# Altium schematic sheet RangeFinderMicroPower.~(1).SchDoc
size A
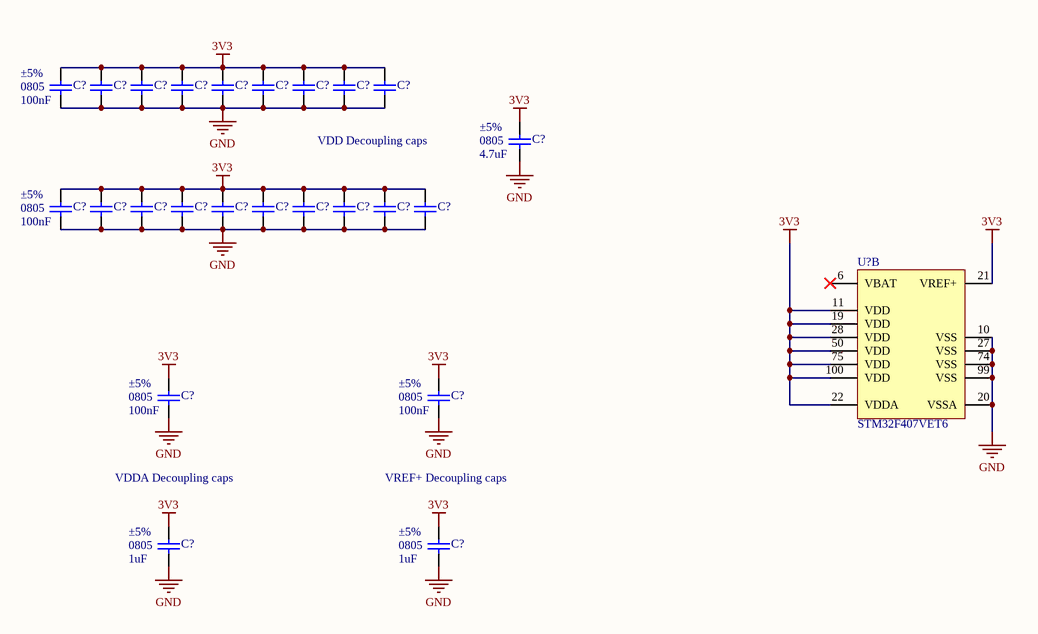
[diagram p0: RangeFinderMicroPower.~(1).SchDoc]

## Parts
(Parts that share a designator on the sheet are numbered #1, #2 ... from top to bottom, then left to right.)
C?#1  value 100nF  Tolerance: ±5%  Case-EIA: 0805  [CAPC0805(2012)100_L]  (hidden comment: CAP 100nF 6.3V 0805(2012))
C?#2  CAP 100nF 6.3V 0805(2012)  [CAPC0805(2012)100_L]  (value not drawn)
C?#3  CAP 100nF 6.3V 0805(2012)  [CAPC0805(2012)100_L]  (value not drawn)
C?#4  CAP 100nF 6.3V 0805(2012)  [CAPC0805(2012)100_L]  (value not drawn)
C?#5  CAP 100nF 6.3V 0805(2012)  [CAPC0805(2012)100_L]  (value not drawn)
C?#6  CAP 100nF 6.3V 0805(2012)  [CAPC0805(2012)100_L]  (value not drawn)
C?#7  CAP 100nF 6.3V 0805(2012)  [CAPC0805(2012)100_L]  (value not drawn)
C?#8  CAP 100nF 6.3V 0805(2012)  [CAPC0805(2012)100_L]  (value not drawn)
C?#9  CAP 100nF 6.3V 0805(2012)  [CAPC0805(2012)100_L]  (value not drawn)
C?#10  value 4.7uF  Case-EIA: 0805  Tolerance: ±5%  [CAPC0805(2012)145_N]  (hidden comment: CAP 4.7uF 6.3V 0805(2012))
C?#11  value 100nF  Tolerance: ±5%  Case-EIA: 0805  [CAPC0805(2012)100_L]  (hidden comment: CAP 100nF 6.3V 0805(2012))
C?#12  CAP 100nF 6.3V 0805(2012)  [CAPC0805(2012)100_L]  (value not drawn)
C?#13  CAP 100nF 6.3V 0805(2012)  [CAPC0805(2012)100_L]  (value not drawn)
C?#14  CAP 100nF 6.3V 0805(2012)  [CAPC0805(2012)100_L]  (value not drawn)
C?#15  CAP 100nF 6.3V 0805(2012)  [CAPC0805(2012)100_L]  (value not drawn)
C?#16  CAP 100nF 6.3V 0805(2012)  [CAPC0805(2012)100_L]  (value not drawn)
C?#17  CAP 100nF 6.3V 0805(2012)  [CAPC0805(2012)100_L]  (value not drawn)
C?#18  CAP 100nF 6.3V 0805(2012)  [CAPC0805(2012)100_L]  (value not drawn)
C?#19  CAP 100nF 6.3V 0805(2012)  [CAPC0805(2012)100_L]  (value not drawn)
C?#20  CAP 100nF 6.3V 0805(2012)  [CAPC0805(2012)100_L]  (value not drawn)
C?#21  value 100nF  Tolerance: ±5%  Case-EIA: 0805  [CAPC0805(2012)100_L]  (hidden comment: CAP 100nF 6.3V 0805(2012))
C?#22  value 100nF  Tolerance: ±5%  Case-EIA: 0805  [CAPC0805(2012)100_L]  (hidden comment: CAP 100nF 6.3V 0805(2012))
C?#23  value 1uF  Case-EIA: 0805  Tolerance: ±5%  [CAPC0805(2012)145_N]  (hidden comment: CAP 1uF 6.3V 0805(2012))
C?#24  value 1uF  Case-EIA: 0805  Tolerance: ±5%  [CAPC0805(2012)145_N]  (hidden comment: CAP 1uF 6.3V 0805(2012))
U?  STM32F407VET6  [STM-LQFP100_M]  (part B of 2)

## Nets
3V3: C?#1.2 C?#2.2 C?#3.2 C?#4.2 C?#5.2 C?#6.2 C?#7.2 C?#8.2 C?#9.2 C?#10.2 C?#11.2 C?#12.2 C?#13.2 C?#14.2 C?#15.2 C?#16.2 C?#17.2 C?#18.2 C?#19.2 C?#20.2 C?#21.2 C?#22.2 C?#23.2 C?#24.2 U?.11(VDD) U?.19(VDD) U?.21(VREF+) U?.22(VDDA) U?.28(VDD) U?.50(VDD) U?.75(VDD) U?.100(VDD)
GND: C?#1.1 C?#2.1 C?#3.1 C?#4.1 C?#5.1 C?#6.1 C?#7.1 C?#8.1 C?#9.1 C?#10.1 C?#11.1 C?#12.1 C?#13.1 C?#14.1 C?#15.1 C?#16.1 C?#17.1 C?#18.1 C?#19.1 C?#20.1 C?#21.1 C?#22.1 C?#23.1 C?#24.1 U?.10(VSS) U?.20(VSSA) U?.27(VSS) U?.74(VSS) U?.99(VSS)

Not connected (* = marked no-connect by the designer): U? 6(VBAT)*

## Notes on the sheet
- (near C?#8) VDD Decoupling caps
- VDDA Decoupling caps
- VREF+ Decoupling caps

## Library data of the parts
C?#1 C?#11 C?#21 C?#22 = CMP-1036-04390-1: CAP 100nF 6.3V ±5% 0805 (2012 Metric) Thickness 1mm SMD; Case-Metric: 2012
C?#2-C?#9 C?#12-C?#20 = CMP-1036-04390-1: CAP 100nF 6.3V ±5% 0805 (2012 Metric) Thickness 1mm SMD; Case-Metric: 2012; Case-EIA: 0805
C?#10 = CMP-1036-04781-1: CAP 4.7uF 6.3V ±5% 0805 (2012 Metric) Thickness 1.45mm SMD; Case-Metric: 2012
C?#23 C?#24 = CMP-1036-04781-1: CAP 1uF 6.3V ±5% 0805 (2012 Metric) Thickness 1.45mm SMD; Case-Metric: 2012
U? = CMP-0243-00016-3: ARM Cortex-M4 32-bit MCU+FPU, 210 DMIPS, 512 kB Flash, 192 kB Internal RAM, 82 I/Os, 100-pin LQFP, -40 to 85 degC, Tray; Manufacturer: STMicroelectronics; Supply Voltage(Vcc) max (V): 3.6; Supply Voltage(Vcc) min (V): 1.8; I/Os (High Current): 82; FLASH Size (Prog) (kB): 512; Operating Frequency(F) (Processor speed) (MHz): 168; D/A Converter: 2x12-bit; Internal RAM Size (kB): 192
